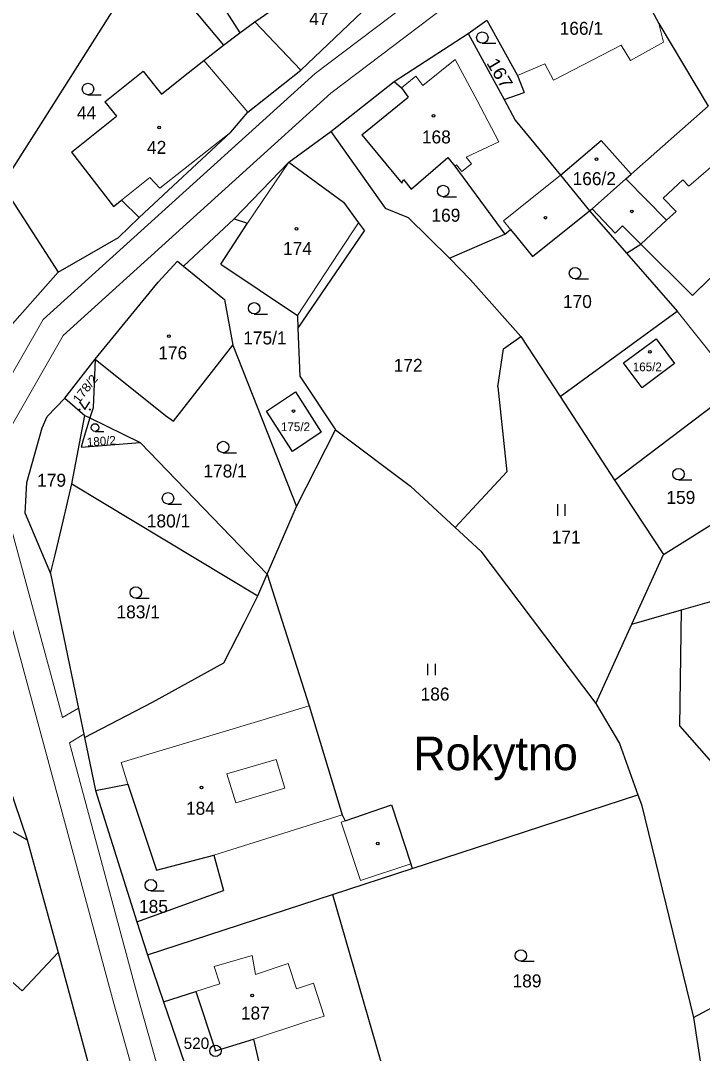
# Model space of a CAD drawing. Extents: x -633485 to -630509, y -1112692 to -1108818.
# Drawn here: x -631976.6 to -631887.2, y -1111853.5 to -1111718.1 of the extents above; entities that cross this region are included whole.
import ezdxf
from ezdxf.enums import TextEntityAlignment as Align

# ---------------------------------------------------------------- set-up
doc = ezdxf.new("R2010")
doc.units = 0
doc.header["$LTSCALE"] = 0.68
for name, color, linetype, lineweight in [('1', 7, 'Continuous', 25), ('13', 7, 'Continuous', 13), ('3', 7, 'Continuous', 25), ('4', 7, 'Continuous', 13), ('5', 7, 'Continuous', 25), ('7', 7, 'Continuous', 13), ('8', 7, 'Continuous', 25)]:
    doc.layers.add(name, color=color, linetype=linetype, lineweight=lineweight)
doc.layers.add('2', color=7, linetype='Continuous')

msp = doc.modelspace()

# ---------------------------------------------------------------- linework, layer by layer
at = {"layer": '1'}
for p, q in [((-631897.93, -1111708.91), (-631892.89, -1111718.42)), ((-631955.91, -1111714.17), (-631949.96, -1111721.29)), ((-631945.88, -1111718.19), (-631938.92, -1111713.4)), ((-631939.82, -1111724.55), (-631930.86, -1111716.02)), ((-631974.18, -1111732.05), (-631964.04, -1111716.07)), ((-631949.92, -1111716.39), (-631947.83, -1111719.66)), ((-631947.83, -1111719.66), (-631945.88, -1111718.19)), ((-631945.88, -1111718.19), (-631939.82, -1111724.55)), ((-631917.89, -1111719.74), (-631915.46, -1111717.97)), ((-631915.46, -1111717.97), (-631911.4, -1111725.24)), ((-631892.89, -1111718.42), (-631886.41, -1111729.28)), ((-631949.96, -1111721.29), (-631947.83, -1111719.66)), ((-631927.58, -1111726.03), (-631917.89, -1111719.74)), ((-631917.89, -1111719.74), (-631913.18, -1111728.41)), ((-631952.57, -1111723.27), (-631949.96, -1111721.29)), ((-631955.21, -1111725.38), (-631952.57, -1111723.27)), ((-631965.53, -1111728.7), (-631960.51, -1111724.69)), ((-631960.51, -1111724.69), (-631959.02, -1111726.56)), ((-631958.11, -1111727.7), (-631955.21, -1111725.38)), ((-631946.78, -1111730.07), (-631939.82, -1111724.55)), ((-631911.4, -1111725.24), (-631910.55, -1111727.47)), ((-631959.02, -1111726.56), (-631958.11, -1111727.7)), ((-631935.9, -1111732.6), (-631927.58, -1111726.03)), ((-631927.58, -1111726.03), (-631926.64, -1111726.87)), ((-631926.64, -1111726.87), (-631925.75, -1111728.09)), ((-631931.83, -1111733.02), (-631925.75, -1111728.09)), ((-631913.18, -1111728.41), (-631910.55, -1111727.47)), ((-631965.53, -1111728.7), (-631964.03, -1111730.57)), ((-631913.18, -1111728.41), (-631911.72, -1111731.11)), ((-631896.52, -1111738.17), (-631886.41, -1111729.28)), ((-631969.92, -1111735.32), (-631964.03, -1111730.57)), ((-631949.03, -1111732.67), (-631946.78, -1111730.07)), ((-631978.99, -1111739.63), (-631974.18, -1111732.05)), ((-631911.72, -1111731.11), (-631905.77, -1111738.3)), ((-631961.02, -1111743.88), (-631949.03, -1111732.67)), ((-631941.4, -1111736.61), (-631935.9, -1111732.6)), ((-631935.9, -1111732.6), (-631928.76, -1111742.63)), ((-631931.83, -1111733.02), (-631926.59, -1111739.39)), ((-631905.77, -1111738.3), (-631900.46, -1111733.79)), ((-631896.52, -1111738.17), (-631900.46, -1111733.79)), ((-631969.92, -1111735.32), (-631964.4, -1111742.44)), ((-631925.35, -1111740.17), (-631920.55, -1111736.02)), ((-631920.55, -1111736.02), (-631919.64, -1111737.14)), ((-631948.6, -1111744.05), (-631941.4, -1111736.61)), ((-631941.4, -1111736.61), (-631934.22, -1111741.86)), ((-631919.64, -1111737.14), (-631913.1, -1111746.08)), ((-631926.59, -1111739.39), (-631926.38, -1111738.89)), ((-631926.38, -1111738.89), (-631925.35, -1111740.17)), ((-631901.65, -1111742.72), (-631897.23, -1111738.8)), ((-631897.23, -1111738.8), (-631896.52, -1111738.17)), ((-631978.99, -1111739.63), (-631971.65, -1111751.05)), ((-631964.4, -1111742.44), (-631963.35, -1111741.6)), ((-631963.35, -1111741.6), (-631961.02, -1111743.88)), ((-631934.22, -1111741.86), (-631932.26, -1111744.56)), ((-631928.76, -1111742.63), (-631925.77, -1111743.86)), ((-631909.47, -1111749), (-631901.99, -1111743.02)), ((-631901.99, -1111743.02), (-631897.14, -1111748.57)), ((-631888.48, -1111754.09), (-631876.4, -1111742.27)), ((-631963.77, -1111746.5), (-631961.02, -1111743.88)), ((-631955.21, -1111750.27), (-631948.6, -1111744.05)), ((-631948.6, -1111744.05), (-631946.83, -1111744.61)), ((-631925.77, -1111743.86), (-631920.34, -1111749.19)), ((-631950.34, -1111750), (-631946.83, -1111744.61)), ((-631940.22, -1111758.41), (-631931.48, -1111745.63)), ((-631932.26, -1111744.56), (-631931.48, -1111745.63)), ((-631913.1, -1111746.08), (-631912.32, -1111745.46)), ((-631912.32, -1111745.46), (-631911.52, -1111746.44)), ((-631971.65, -1111751.05), (-631963.77, -1111746.5)), ((-631920.34, -1111749.19), (-631913.1, -1111746.08)), ((-631911.52, -1111746.44), (-631909.47, -1111749)), ((-631897.14, -1111748.57), (-631895.25, -1111747.35)), ((-631895.25, -1111747.35), (-631888.48, -1111754.09)), ((-631958.53, -1111752.36), (-631956.01, -1111749.62)), ((-631956.01, -1111749.62), (-631955.21, -1111750.27)), ((-631920.34, -1111749.19), (-631917.6, -1111752.03)), ((-631897.14, -1111748.57), (-631890.47, -1111756.17)), ((-631978.36, -1111758.59), (-631971.65, -1111751.05)), ((-631955.21, -1111750.27), (-631949.84, -1111754.61)), ((-631950.34, -1111750), (-631940.29, -1111756.72)), ((-631966.79, -1111762.47), (-631958.53, -1111752.36)), ((-631917.6, -1111752.03), (-631911, -1111759.47)), ((-631949.84, -1111754.61), (-631948.74, -1111760.6)), ((-631905.84, -1111767.36), (-631890.47, -1111756.17)), ((-631940.29, -1111756.72), (-631940.22, -1111758.41)), ((-631940.22, -1111758.41), (-631939.97, -1111764.69)), ((-631956.54, -1111770.59), (-631948.74, -1111760.6)), ((-631948.74, -1111760.6), (-631940.4, -1111781.77)), ((-631913.26, -1111761.09), (-631911, -1111759.47)), ((-631911, -1111759.47), (-631905.84, -1111767.36)), ((-631897.5, -1111762.95), (-631893.24, -1111759.77)), ((-631893.24, -1111759.77), (-631890.81, -1111763.03)), ((-631913.99, -1111766.1), (-631913.26, -1111761.09)), ((-631970.77, -1111767.59), (-631966.79, -1111762.47)), ((-631966.79, -1111762.47), (-631967.07, -1111768.82)), ((-631966.79, -1111762.47), (-631957.58, -1111769.86)), ((-631897.15, -1111763.42), (-631897.5, -1111762.95)), ((-631896.25, -1111764.63), (-631897.15, -1111763.42)), ((-631890.81, -1111763.03), (-631894.86, -1111766.05)), ((-631939.97, -1111764.69), (-631935.28, -1111771.74)), ((-631895.07, -1111766.21), (-631896.25, -1111764.63)), ((-631913.99, -1111766.1), (-631912.82, -1111777.21)), ((-631898.71, -1111778.33), (-631882.56, -1111766.1)), ((-631894.86, -1111766.05), (-631895.07, -1111766.21)), ((-631944.36, -1111769.27), (-631940.55, -1111766.74)), ((-631940.55, -1111766.74), (-631937.18, -1111772.02)), ((-631905.84, -1111767.36), (-631898.71, -1111778.33)), ((-631973.09, -1111769.96), (-631970.77, -1111767.59)), ((-631970.77, -1111767.59), (-631968.18, -1111769.83)), ((-631967.07, -1111768.82), (-631967.49, -1111770.17)), ((-631973.76, -1111771.44), (-631973.09, -1111769.96)), ((-631969.85, -1111778.82), (-631968.18, -1111769.83)), ((-631967.49, -1111770.17), (-631968.39, -1111773.05)), ((-631957.58, -1111769.86), (-631956.54, -1111770.59)), ((-631940.95, -1111774.55), (-631944.36, -1111769.27)), ((-631975.77, -1111778.62), (-631973.76, -1111771.44)), ((-631937.18, -1111772.02), (-631940.95, -1111774.55)), ((-631940.4, -1111781.77), (-631935.28, -1111771.74)), ((-631935.28, -1111771.74), (-631925.44, -1111779.1)), ((-631968.39, -1111773.05), (-631968.63, -1111774.01)), ((-631968.63, -1111774.01), (-631960.89, -1111773.37)), ((-631960.89, -1111773.37), (-631944.26, -1111790.67)), ((-631917.9, -1111782.69), (-631912.82, -1111777.21)), ((-631898.71, -1111778.33), (-631892.26, -1111788.08)), ((-631976.01, -1111782.68), (-631975.77, -1111778.62)), ((-631971.02, -1111783.71), (-631969.85, -1111778.82)), ((-631969.85, -1111778.82), (-631945.49, -1111793.48)), ((-631925.44, -1111779.1), (-631919.59, -1111784.52)), ((-631944.26, -1111790.67), (-631940.4, -1111781.77)), ((-631892.26, -1111788.08), (-631881.46, -1111781.3)), ((-631976.01, -1111782.68), (-631972.66, -1111790.58)), ((-631972.07, -1111788.13), (-631971.02, -1111783.71)), ((-631919.59, -1111784.52), (-631917.9, -1111782.69)), ((-631919.59, -1111784.52), (-631916.23, -1111787.63)), ((-631916.23, -1111787.63), (-631901.15, -1111807.62)), ((-631972.66, -1111790.58), (-631972.07, -1111788.13)), ((-631896.42, -1111797.21), (-631892.26, -1111788.08)), ((-631972.66, -1111790.58), (-631968.19, -1111812.07)), ((-631945.49, -1111793.48), (-631944.26, -1111790.67)), ((-631944.26, -1111790.67), (-631938.74, -1111807.94)), ((-631889.92, -1111795.35), (-631875.1, -1111791.1)), ((-631947.21, -1111796.99), (-631945.49, -1111793.48)), ((-631896.42, -1111797.21), (-631889.92, -1111795.35)), ((-631890.13, -1111810.57), (-631889.92, -1111795.35)), ((-631949.94, -1111802.27), (-631947.21, -1111796.99)), ((-631901.15, -1111807.62), (-631896.42, -1111797.21)), ((-631959.28, -1111807.44), (-631949.94, -1111802.27)), ((-631968.19, -1111812.07), (-631959.28, -1111807.44)), ((-631938.74, -1111807.94), (-631934.42, -1111822.21)), ((-631901.15, -1111807.62), (-631898.03, -1111812.87)), ((-631890.13, -1111810.57), (-631874.62, -1111828.29)), ((-631968.19, -1111812.07), (-631966.78, -1111819.04)), ((-631898.03, -1111812.87), (-631895.64, -1111819.59)), ((-631978.28, -1111818.02), (-631975.72, -1111825.48)), ((-631966.78, -1111819.04), (-631962.54, -1111818.18)), ((-631962.54, -1111818.18), (-631958.76, -1111829.49)), ((-631966.78, -1111819.04), (-631961.33, -1111836.27)), ((-631925.22, -1111829.25), (-631895.64, -1111819.59)), ((-631895.64, -1111819.59), (-631895.14, -1111820.88)), ((-631934.04, -1111823.02), (-631927.94, -1111820.92)), ((-631927.94, -1111820.92), (-631925.42, -1111828.64)), ((-631895.14, -1111820.88), (-631888.32, -1111848.82)), ((-631934.42, -1111822.21), (-631934.04, -1111823.02)), ((-631978.57, -1111823.88), (-631975.72, -1111825.48)), ((-631975.72, -1111825.48), (-631971.67, -1111840.26)), ((-631958.76, -1111829.49), (-631951.23, -1111827.49)), ((-631951.23, -1111827.49), (-631950, -1111832.13)), ((-631935.68, -1111832.67), (-631925.22, -1111829.25)), ((-631925.42, -1111828.64), (-631925.22, -1111829.25)), ((-631961.33, -1111836.27), (-631950, -1111832.13)), ((-631990.41, -1111832.98), (-631976.39, -1111845.3)), ((-631959.96, -1111840.6), (-631935.68, -1111832.67)), ((-631935.68, -1111832.67), (-631927.63, -1111860.54)), ((-631961.33, -1111836.27), (-631959.96, -1111840.6)), ((-631888.32, -1111848.82), (-631866.42, -1111836.9)), ((-631971.67, -1111840.26), (-631976.39, -1111845.3)), ((-631971.67, -1111840.26), (-631961.88, -1111876.36)), ((-631959.96, -1111840.6), (-631957.85, -1111846.76)), ((-631957.85, -1111846.76), (-631953.59, -1111845.37)), ((-631953.59, -1111845.37), (-631951.04, -1111853.18)), ((-631957.85, -1111846.76), (-631952.09, -1111863.51)), ((-631888.32, -1111848.82), (-631887.21, -1111856.22)), ((-631951.04, -1111853.18), (-631946.06, -1111851.62)), ((-631946.06, -1111851.62), (-631943.49, -1111862.52))]:
    msp.add_line(p, q, dxfattribs=at)
for points in [[(-631905.77, -1111738.3), (-631901.99, -1111743.02), (-631901.65, -1111742.72)], [(-631968.18, -1111769.83), (-631967.49, -1111770.17), (-631960.89, -1111773.37)]]:
    msp.add_lwpolyline(points, dxfattribs=at)
at = {"layer": '13'}
for points in [[(-631916.51, -1111708.73), (-631937.96, -1111724.98), (-631973.62, -1111757.27), (-631983.84, -1111775.09), (-631973.7, -1111812.39), (-631964.38, -1111846.95), (-631945.65, -1111913.51)], [(-631942.03, -1111914.22), (-631961.2, -1111846.09), (-631970.19, -1111812.76), (-631968.28, -1111811.65), (-631968.99, -1111808.24), (-631971.08, -1111809.45), (-631980.3, -1111775.55), (-631971.02, -1111759.37), (-631935.9, -1111727.56), (-631914.51, -1111711.36)]]:
    msp.add_lwpolyline(points, dxfattribs=at)
msp.add_lwpolyline([(-631882.56, -1111766.1), (-631878.7, -1111763.37), (-631875.61, -1111761.5), (-631877.38, -1111758.62), (-631872.38, -1111755.63), (-631870.01, -1111754.36), (-631876.4, -1111742.27), (-631888.48, -1111754.09), (-631895.25, -1111747.35), (-631897.14, -1111748.57), (-631890.47, -1111756.17)], close=True, dxfattribs=at)
at = {"layer": '3'}
for p, q in [((-631916.033, -1111721.03), (-631914.283, -1111721.03)), ((-631967.753, -1111727.77), (-631966.003, -1111727.77)), ((-631921.183, -1111741.15), (-631919.433, -1111741.15)), ((-631903.873, -1111751.93), (-631902.123, -1111751.93)), ((-631945.963, -1111756.53), (-631944.213, -1111756.53)), ((-631966.825, -1111771.92), (-631965.653, -1111771.92)), ((-631950.013, -1111774.73), (-631948.263, -1111774.73)), ((-631890.313, -1111778.29), (-631888.563, -1111778.29)), ((-631957.253, -1111781.46), (-631955.503, -1111781.46)), ((-631906.151, -1111782.99), (-631906.151, -1111781.49)), ((-631905.15, -1111782.99), (-631905.15, -1111781.49)), ((-631961.483, -1111793.8), (-631959.733, -1111793.8)), ((-631923.191, -1111803.9), (-631923.191, -1111802.4)), ((-631922.19, -1111803.9), (-631922.19, -1111802.4)), ((-631959.503, -1111832.2), (-631957.753, -1111832.2)), ((-631910.973, -1111841.43), (-631909.223, -1111841.43))]:
    msp.add_line(p, q, dxfattribs=at)
msp.add_lwpolyline([(-631968.85, -1111768.054), (-631968.18, -1111769.06), (-631967.51, -1111768.054)], dxfattribs=at)
for centre, radius in [((-631916.0329, -1111720.2798), 0.75), ((-631967.7529, -1111727.0198), 0.75), ((-631921.1829, -1111740.3998), 0.75), ((-631903.8729, -1111751.1798), 0.75), ((-631945.9629, -1111755.7798), 0.75), ((-631968.85, -1111769.0596), 0.067), ((-631967.51, -1111769.0596), 0.067), ((-631966.8252, -1111771.4174), 0.5025), ((-631950.0129, -1111773.9798), 0.75), ((-631890.3129, -1111777.5398), 0.75), ((-631957.2529, -1111780.7098), 0.75), ((-631961.4829, -1111793.0498), 0.75), ((-631959.5029, -1111831.4498), 0.75), ((-631910.9729, -1111840.6798), 0.75)]:
    msp.add_circle(centre, radius, dxfattribs=at)
at = {"layer": '4'}
for p, q in [((-631892.89, -1111718.42), (-631892.28, -1111720.87)), ((-631906.71, -1111725.88), (-631897.82, -1111721.28)), ((-631897.82, -1111721.28), (-631896.61, -1111723.26)), ((-631896.61, -1111723.26), (-631892.28, -1111720.87)), ((-631952.57, -1111723.27), (-631946.78, -1111730.07)), ((-631923.84, -1111726.55), (-631919.6, -1111723.13)), ((-631919.6, -1111723.13), (-631916.73, -1111728.54)), ((-631911.4, -1111725.24), (-631907.83, -1111723.71)), ((-631907.83, -1111723.71), (-631906.71, -1111725.88)), ((-631926.64, -1111726.87), (-631924.74, -1111725.32)), ((-631924.74, -1111725.32), (-631923.84, -1111726.55)), ((-631916.73, -1111728.54), (-631913.86, -1111733.94)), ((-631958.33, -1111740.03), (-631949.03, -1111732.67)), ((-631918.17, -1111735.95), (-631913.86, -1111733.94)), ((-631888.96, -1111739.77), (-631882.93, -1111734.57)), ((-631918.17, -1111735.95), (-631917.46, -1111736.82)), ((-631946.83, -1111744.61), (-631941.4, -1111736.61)), ((-631919.64, -1111737.14), (-631919.42, -1111736.96)), ((-631919.42, -1111736.96), (-631918.72, -1111737.82)), ((-631918.72, -1111737.82), (-631917.46, -1111736.82)), ((-631963.35, -1111741.6), (-631959.64, -1111738.64)), ((-631959.64, -1111738.64), (-631958.33, -1111740.03)), ((-631913.26, -1111744.29), (-631905.77, -1111738.3)), ((-631891.87, -1111744.22), (-631897.23, -1111738.8)), ((-631892.33, -1111741.33), (-631889.72, -1111738.94)), ((-631889.72, -1111738.94), (-631888.96, -1111739.77)), ((-631892.33, -1111741.33), (-631890.62, -1111743.07)), ((-631891.87, -1111744.22), (-631890.62, -1111743.07)), ((-631913.26, -1111744.29), (-631912.32, -1111745.46)), ((-631895.25, -1111747.35), (-631891.87, -1111744.22)), ((-631934.85, -1111748.48), (-631932.26, -1111744.56)), ((-631940.29, -1111756.72), (-631934.85, -1111748.48)), ((-631944.64, -1111809.71), (-631938.74, -1111807.94)), ((-631963.39, -1111815.36), (-631944.64, -1111809.71)), ((-631963.39, -1111815.36), (-631962.54, -1111818.18)), ((-631949.53, -1111816.84), (-631943.07, -1111814.94)), ((-631943.07, -1111814.94), (-631941.94, -1111818.7)), ((-631949.53, -1111816.84), (-631948.37, -1111820.64)), ((-631948.37, -1111820.64), (-631941.94, -1111818.7)), ((-631951.23, -1111827.49), (-631934.42, -1111822.21)), ((-631934.54, -1111823.18), (-631934.04, -1111823.02)), ((-631934.54, -1111823.18), (-631932.03, -1111830.85)), ((-631932.03, -1111830.85), (-631925.42, -1111828.64)), ((-631951.19, -1111842.12), (-631946.23, -1111840.67)), ((-631946.23, -1111840.67), (-631945.79, -1111843.14)), ((-631945.79, -1111843.14), (-631941.51, -1111841.71)), ((-631941.51, -1111841.71), (-631940.4, -1111845.02)), ((-631951.19, -1111842.12), (-631950.47, -1111844.38)), ((-631953.59, -1111845.37), (-631950.47, -1111844.38)), ((-631940.4, -1111845.02), (-631938.18, -1111844.31)), ((-631938.18, -1111844.31), (-631936.79, -1111848.61)), ((-631939.04, -1111849.33), (-631936.79, -1111848.61)), ((-631946.06, -1111851.62), (-631939.04, -1111849.33))]:
    msp.add_line(p, q, dxfattribs=at)
msp.add_lwpolyline([(-631895.25, -1111747.35), (-631897.64, -1111744.97), (-631898.61, -1111745.95), (-631901.65, -1111742.72)], dxfattribs=at)
at = {"layer": '5'}
for centre in [(-631922.4268, -1111730.5492), (-631958.4368, -1111732.0692), (-631901.0668, -1111736.2192), (-631896.4368, -1111743.0692), (-631907.7668, -1111743.8992), (-631940.4068, -1111745.3592), (-631957.1568, -1111759.4292), (-631894.0468, -1111761.4892), (-631940.7868, -1111769.2592), (-631952.8668, -1111818.6392), (-631929.7568, -1111825.9892), (-631946.2268, -1111845.9192)]:
    msp.add_circle(centre, 0.175, dxfattribs=at)
at = {"layer": '8'}
for radius in [0.75, 0.03]:
    msp.add_circle((-631951.04, -1111853.1798), radius, dxfattribs=at)

# ---------------------------------------------------------------- texts
at = {"layer": '2'}
for s, p in [('47', (-631938.74, -1111718.645)), ('44', (-631969.2, -1111730.985)), ('168', (-631923.96, -1111734.155)), ('42', (-631960.01, -1111735.525)), ('169', (-631922.71, -1111744.425)), ('174', (-631942.17, -1111748.785)), ('170', (-631905.46, -1111755.745)), ('176', (-631958.53, -1111762.465)), ('172', (-631927.66, -1111764.115)), ('179', (-631974.42, -1111779.185)), ('159', (-631891.89, -1111781.435)), ('171', (-631906.93, -1111786.635)), ('183/1', (-631964.01, -1111796.445)), ('186', (-631924.13, -1111807.225)), ('184', (-631954.9, -1111822.205)), ('185', (-631961.06, -1111835.075)), ('189', (-631912.07, -1111844.845)), ('187', (-631947.7, -1111849.065))]:
    msp.add_text(s, height=1.7, dxfattribs=at).set_placement(p)
for s, height, p in [('166/1', 1.7, (-631903.05, -1111719.912)), ('166/2', 1.7, (-631901.35, -1111739.622)), ('175/1', 1.7, (-631944.55, -1111760.522)), ('165/2', 1.139, (-631894.4, -1111764.034)), ('175/2', 1.14, (-631940.539, -1111771.89)), ('178/1', 1.7, (-631949.77, -1111777.972)), ('180/1', 1.7, (-631957.19, -1111784.522))]:
    msp.add_text(s, height=height, dxfattribs=at).set_placement(p, align=Align.CENTER)
at = {"layer": '2', "width": 1.1}
msp.add_text('167', height=1.7, rotation=301, dxfattribs=at).set_placement((-631915.544, -1111723.608))
msp.add_text('178/2', height=1.139, rotation=52, dxfattribs=at).set_placement((-631967.6657, -1111766.6961), align=Align.CENTER)
at = {"layer": '2'}
msp.add_text('180/2', height=1.139, rotation=4, dxfattribs=at).set_placement((-631965.9587, -1111773.775), align=Align.CENTER)
at = {"layer": '7'}
msp.add_text('Rokytno', height=4.4, dxfattribs=at).set_placement((-631914.299, -1111816.36), align=Align.CENTER)
at = {"layer": '8'}
msp.add_text('520', height=1.5, dxfattribs=at).set_placement((-631955.2, -1111852.925))

doc.saveas('drawing.dxf')
